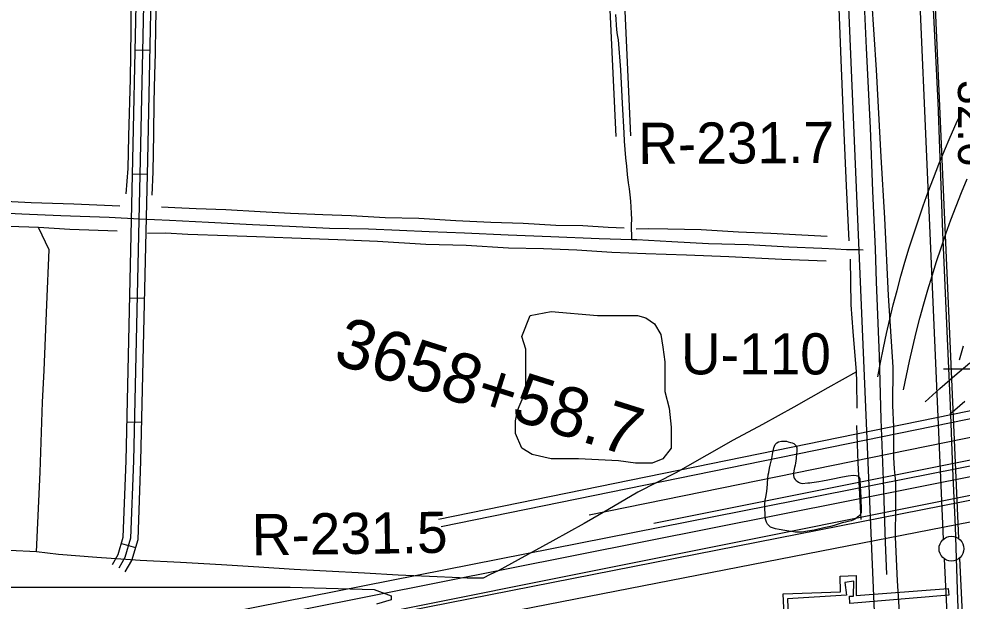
# Model space of a CAD drawing. Extents: x 3313447 to 3351316, y 703786 to 729172.
# Drawn here: x 3320382 to 3322283, y 721813 to 722988 of the extents above; entities that cross this region are included whole.
import ezdxf

# ---------------------------------------------------------------- set-up
doc = ezdxf.new("R2010")
doc.units = 0
for name, color, linetype in [('V-DTCH-CNTR', 7, 'Continuous'), ('V-FLOD-BASE', 7, 'Continuous'), ('V-LEVE-TOET', 7, 'Continuous'), ('V-RIVR-RANG', 7, 'Continuous'), ('V-RIVR-RANG-IDEN', 7, 'Continuous'), ('V-ROAD-CNTR', 7, 'Continuous'), ('V-SITE-VEGE', 7, 'Continuous'), ('V-SURV-IDEN', 7, 'Continuous'), ('V-SURV-LINE', 7, 'Continuous'), ('V-TOPO-SHOR', 7, 'Continuous'), ('V-UTIL-LINE', 7, 'Continuous')]:
    doc.layers.add(name, color=color, linetype=linetype)

msp = doc.modelspace()

# ---------------------------------------------------------------- linework, layer by layer
at = {"layer": 'V-DTCH-CNTR'}
msp.add_lwpolyline([(3321617.4, 722542.8), (3321616.9, 722552.9), (3321616.7, 722562.9), (3321616.6, 722573), (3321616.8, 722583.1), (3321616.4, 722595.5), (3321615.7, 722607.8), (3321614.8, 722620.1), (3321613.7, 722632.4), (3321612.3, 722644.7), (3321610.7, 722656.9), (3321608.6, 722673.7), (3321606.7, 722690.5), (3321605.1, 722707.3), (3321603.7, 722724.1), (3321602.5, 722741), (3321601.6, 722757.9), (3321598.2, 722816.7), (3321594.6, 722884.5), (3321589.9, 722945.4), (3321588.4, 722955.5), (3321587.2, 722965.7), (3321586.3, 722975.8), (3321585.6, 722986), (3321585.1, 722996.2)], dxfattribs=at)
at = {"layer": 'V-FLOD-BASE'}
msp.add_lwpolyline([(3322294, 721368.1), (3322281.2, 721662.8), (3322274.1, 721816), (3322269.7, 721963), (3322263.9, 722080.1), (3322259.4, 722208.1), (3322252.3, 722357.9), (3322244, 722557.3), (3322234.5, 722819.4), (3322223.5, 723034.5), (3322212.5, 723259.8), (3322203.5, 723485.2), (3322191.4, 723776.5), (3322185.6, 723936.5), (3322185.3, 724050.8), (3322186.1, 724129.8), (3322189, 724191.7), (3322188.8, 724355.1), (3322190.1, 724588.6), (3322195.6, 724641), (3322197.1, 724671.6), (3322196.5, 724713.1), (3322192.5, 724744.4), (3322195.1, 724942.5)], dxfattribs=at)
at = {"layer": 'V-LEVE-TOET'}
msp.add_lwpolyline([(3322064.2, 723842.4), (3322068.6, 723720.7), (3322071, 723652.9), (3322073, 723597), (3322079.6, 723543.2), (3322085.5, 723402.8), (3322091.4, 723242.7), (3322096.9, 723129.5), (3322100.2, 723028), (3322109.2, 722884.9), (3322118.7, 722709.5), (3322126.2, 722585.8), (3322133.6, 722429.4), (3322143.2, 722285.3), (3322142.6, 722207.6), (3322144.3, 722164.8), (3322144.7, 722103.2), (3322145.5, 722079.9), (3322148.3, 722053.3), (3322148.6, 721983.9), (3322147.7, 721962.7), (3322148, 721942.1), (3322151.5, 721854.1), (3322156.6, 721781.2)], dxfattribs=at)
at = {"layer": 'V-RIVR-RANG'}
msp.add_line((3322245.2, 722282), (3323045.2, 722282.9), dxfattribs=at)
at = {"layer": 'V-ROAD-CNTR'}
for p, q in [((3320616.1, 722924.8), (3320646.1, 722924.2)), ((3320610.8, 722674.9), (3320640.8, 722674.2)), ((3320605.1, 722425), (3320635.1, 722424.3)), ((3320599.5, 722175), (3320629.5, 722174.4)), ((3320588.3, 721929.7), (3320617.1, 721921.2))]:
    msp.add_line(p, q, dxfattribs=at)
for points in [[(3322139.1, 720885.8), (3322130.7, 721205.1), (3322096.5, 722014), (3322054, 723027.2), (3322033, 723634.2), (3322026.6, 723817.2)], [(3321545.5, 723567.8), (3321569, 723091.8), (3321584.6, 722750.1)], [(3321575.6, 723566.5), (3321599, 723093.2), (3321614.6, 722751.4)], [(3320641.2, 723540.4), (3320638.4, 723265.5), (3320626.4, 722703.2), (3320612.7, 722095.9), (3320607, 721940.2), (3320595.6, 721901.3), (3320583.2, 721879.8)], [(3320596.2, 721872.3), (3320609.5, 721895.3), (3320621.9, 721937.7), (3320627.7, 722095.4), (3320641.4, 722702.9), (3320653.4, 723265.3), (3320656.1, 723530.3)], [(3320570.2, 721887.2), (3320581.7, 721907.2), (3320592.1, 721942.6), (3320597.7, 722096.3), (3320611.4, 722703.5), (3320623.4, 723265.7), (3320624.9, 723411.2)], [(3319290.7, 722638.8), (3319343.4, 722637.7), (3319419.2, 722635.4), (3319510.4, 722631.3), (3319596.3, 722628.7), (3319698.5, 722624.6), (3319791.3, 722620.6), (3319890.1, 722615.8), (3319970.8, 722611.8), (3320071, 722606.7), (3320163.8, 722603), (3320240, 722599.6), (3320307.2, 722598.1), (3320388, 722594.4), (3320466.6, 722591.1), (3320563.6, 722587.4), (3320624.6, 722584.4), (3320685.6, 722581.5)], [(3320685.6, 722581.5), (3320763.9, 722577.8), (3320852.3, 722573.1), (3320927.4, 722569.8), (3321007.8, 722565.7), (3321086.1, 722564.1), (3321149, 722561.5), (3321208.5, 722558.9), (3321279.9, 722556), (3321368.2, 722552.2), (3321453.8, 722548.9), (3321551.6, 722544.5), (3321617.4, 722542.8), (3321627.1, 722542.5), (3321697.7, 722538.5), (3321771.8, 722534.8), (3321851.5, 722532.2), (3321933.3, 722527.5), (3321999.7, 722524.9), (3322027.5, 722524.1), (3322049.5, 722522.6), (3322064.4, 722522.3), (3322074.2, 722522.2), (3322083.1, 722521.8)]]:
    msp.add_lwpolyline(points, dxfattribs=at)
at = {"layer": 'V-SITE-VEGE'}
msp.add_lwpolyline([(3321548, 722389.2), (3321628.7, 722389.2), (3321645.6, 722384.9), (3321662.6, 722372.2), (3321675.4, 722350.9), (3321679.6, 722325.5), (3321683.8, 722295.7), (3321683.8, 722236.2), (3321692.3, 722202.3), (3321696.6, 722164), (3321696.6, 722121.5), (3321679.6, 722100.3), (3321658.4, 722091.8), (3321624.4, 722091.8), (3321590.4, 722096.1), (3321509.8, 722100.3), (3321454.6, 722100.3), (3321416.4, 722108.8), (3321395.2, 722121.5), (3321382.4, 722151.3), (3321382.4, 722176.8), (3321386.7, 722198), (3321399.4, 722227.7), (3321403.6, 722249), (3321403.6, 722321.2), (3321395.2, 722346.7), (3321412.1, 722389.2), (3321454.6, 722397.7)], close=True, dxfattribs=at)
for points in [[(3321948.2, 722056.7), (3321950.4, 722055), (3321952.9, 722053.4), (3321955.9, 722052), (3321957.8, 722051.3), (3321960.5, 722050.6), (3321971.6, 722051.8), (3321975.7, 722051.9), (3321979.6, 722052.4), (3321984.7, 722052.9), (3321994.1, 722054.5), (3322001.3, 722055.8), (3322011.8, 722058), (3322018.6, 722059.2), (3322041.4, 722063.9), (3322053.3, 722066.1), (3322063.2, 722067.2), (3322068.9, 722066.8), (3322071.7, 722066), (3322073.8, 722065.1), (3322076.4, 722060.7), (3322076.9, 722057.4), (3322077.4, 722045.1), (3322078.8, 722022.1), (3322078.8, 722014.2), (3322079.1, 722002.8), (3322079.1, 721999.2), (3322079.4, 721996.4), (3322079.4, 721993.8), (3322079, 721991.1), (3322077.8, 721988.6), (3322076.4, 721986.6), (3322074.5, 721984.4), (3322072.2, 721982.5), (3322067.6, 721979.3), (3322062.6, 721976.7), (3322058.8, 721975.5), (3322052.6, 721973.6), (3322048, 721972.5), (3322041.2, 721970.9), (3322025, 721966.1), (3322017.4, 721964.1), (3322004, 721960.8), (3321984.8, 721956.6), (3321971.4, 721954.1), (3321959.9, 721952.6), (3321955.8, 721952.5), (3321950, 721952.5), (3321946.6, 721952.6), (3321938.7, 721953.6), (3321933.6, 721954.4), (3321925.5, 721955.4), (3321913.7, 721957.4), (3321906.8, 721958.9), (3321902.5, 721960.3), (3321896.8, 721962.7), (3321893.9, 721964.9), (3321890.4, 721968.8), (3321888.7, 721972.4), (3321886.8, 721978.9), (3321885.9, 721986.9), (3321885.4, 722002), (3321885.4, 722008.2), (3321886.1, 722017), (3321886.9, 722023), (3321888.9, 722034.6), (3321890.5, 722049.1), (3321890.5, 722052), (3321891.3, 722060.5), (3321892.1, 722067.8), (3321893, 722073), (3321894.7, 722081.5), (3321896.1, 722087.2), (3321897.8, 722095.6), (3321899.1, 722100.8), (3321901.5, 722112.8), (3321902.8, 722118.9), (3321903.5, 722122.6), (3321904.4, 722125.9), (3321905.7, 722129.4), (3321909, 722132.8), (3321912.9, 722134.5), (3321918.9, 722135.6), (3321922.6, 722136), (3321925.2, 722136), (3321928.8, 722135.6), (3321932.2, 722134.8), (3321936.8, 722133.5), (3321939.9, 722132.4), (3321943.3, 722131), (3321945.1, 722129.7), (3321948, 722126.5), (3321949.7, 722122.6), (3321949.9, 722120.1), (3321949.5, 722114.6), (3321949.1, 722111.9), (3321948.2, 722101.1), (3321947, 722091.2), (3321946.3, 722087.8), (3321944.9, 722082.7), (3321943.4, 722075.8)], [(3321943.4, 722075.8), (3321943, 722071.5), (3321943.1, 722066.9), (3321943.6, 722063.5), (3321944.4, 722061.5), (3321946, 722058.8), (3321948.2, 722056.7)], [(3319964.4, 721811.4), (3320011.1, 721828.4), (3320057.8, 721849.7), (3320147, 721858.2), (3320359.3, 721841.2), (3320928.2, 721841.2), (3321098, 721836.9), (3321131.9, 721824.2), (3321131.9, 721815.7), (3321102.2, 721807.2)]]:
    msp.add_lwpolyline(points, dxfattribs=at)
at = {"layer": 'V-SURV-LINE'}
for points in [[(3322245.5, 721938.3), (3322163.8, 723805.4)], [(3322193.8, 723806.7), (3322275.4, 721939.6)], [(3322306.7, 720667.9), (3322247.3, 721898.3)], [(3322277.3, 721899.7), (3322336.6, 720669.3)]]:
    msp.add_lwpolyline(points, dxfattribs=at)
msp.add_circle((3322261.3, 721919), 25, dxfattribs=at)
at = {"layer": 'V-TOPO-SHOR'}
for points in [[(3322131.3, 721867.2), (3322128.2, 721932.4), (3322124.6, 722057.9), (3322119.9, 722180), (3322116.2, 722307), (3322110.3, 722457.5), (3322107.9, 722523.5), (3322103.1, 722640.3), (3322098.2, 722768.1), (3322090, 722928.3), (3322083.8, 723062.5), (3322078.9, 723206.3), (3322075, 723318.1), (3322071.1, 723447.7), (3322068, 723548.8)], [(3320650.5, 722632), (3320652.4, 722679), (3320653.6, 722755.9), (3320654.5, 722819.6), (3320655.7, 722875.6), (3320657.2, 722918), (3320657.7, 722974.1), (3320659.9, 723040.9), (3320662.5, 723093.1), (3320662.7, 723164.4), (3320662.8, 723226.7), (3320665.5, 723301.8), (3320667, 723355.1), (3320668.2, 723402.7), (3320670.5, 723420.1)], [(3320597.7, 722635), (3320602.3, 722686.1), (3320603.5, 722751.2), (3320606.9, 722866.7), (3320607.9, 722964.5), (3320608, 723011.1), (3320609.2, 723054.6), (3320611.4, 723115.1), (3320614.4, 723181.9), (3320614.5, 723249.1), (3320616.5, 723314.5), (3320617.9, 723353.8), (3320618, 723402.7)], [(3322055.2, 722539.6), (3322049.4, 722650.6), (3322045.3, 722758), (3322039.2, 722904.8), (3322036.4, 722974.5), (3322031, 723111.9), (3322027, 723194.8), (3322024.3, 723256.7)], [(3320585.5, 722609.9), (3320492.4, 722613.7), (3320406.4, 722616.3), (3320340.5, 722619.7)], [(3321601.9, 722565.4), (3321569.3, 722567), (3321518.5, 722569.9), (3321464.2, 722571.1), (3321398.1, 722575.1), (3321333.1, 722577), (3321262.5, 722580.3), (3321188, 722584.7), (3321120.1, 722586.6), (3321051.6, 722590.3), (3320994.2, 722592.2), (3320929.5, 722594.8), (3320868.3, 722598.1), (3320798.7, 722602.1), (3320739.2, 722604.7), (3320696.4, 722606.2), (3320669.2, 722607.6)], [(3320580, 722559.7), (3320484.2, 722562.9), (3320421.6, 722566.5), (3320362.1, 722569.1), (3320281.1, 722573.2), (3320181.9, 722577.6), (3320095.3, 722582.4), (3319987.8, 722586.1), (3319888.6, 722591.2), (3319787.7, 722595), (3319670.1, 722600.2), (3319589, 722604.5), (3319509.6, 722605.1)], [(3320417.6, 721912.9), (3320424.9, 722073.4), (3320429.1, 722214.6), (3320433, 722278.5), (3320438.4, 722411.2), (3320443.1, 722521.5), (3320421.6, 722566.5)], [(3322008.8, 722499.1), (3321919.4, 722502.5), (3321812.6, 722507.6), (3321727, 722511), (3321645.6, 722514), (3321577.1, 722516.2), (3321506.1, 722520.9), (3321438.9, 722523.5), (3321368.3, 722525.1), (3321283.4, 722530.2), (3321201.7, 722532.8), (3321104.6, 722538.3), (3321024.9, 722541.7), (3320932, 722545), (3320860.4, 722548.3), (3320802.2, 722550.2), (3320722.6, 722552.9), (3320677, 722555.4), (3320640.9, 722555)], [(3322010.8, 722548.5), (3321960, 722551), (3321897.1, 722554.7), (3321832, 722557.3), (3321756.5, 722562), (3321689.7, 722563.2), (3321650.7, 722564.4), (3321625.5, 722563.1)], [(3322071.3, 722202.7), (3322070.8, 722256.1), (3322069.9, 722275.8), (3322063.3, 722356.9), (3322059.4, 722410.9), (3322058.1, 722502.9)], [(3322069.9, 722275.8), (3322011.9, 722243.3), (3321943.3, 722204.5), (3321880.2, 722169.2), (3321821.3, 722138), (3321768.4, 722107.9), (3321705.6, 722071.9), (3321629, 722033.1), (3321569, 721997.1), (3321521, 721970.1), (3321457.9, 721935.1), (3321387.8, 721896.3), (3321347.8, 721874.5), (3321331.4, 721866.9), (3321317.5, 721859.6), (3321309.8, 721859.3), (3321285.4, 721859.3), (3321224.6, 721862.6), (3321146.3, 721865.9), (3321078.4, 721869.6), (3321000.8, 721873.6), (3320936.5, 721877.3), (3320865.2, 721882), (3320790, 721886.7), (3320707.6, 721891.1), (3320626.1, 721895.5), (3320538.8, 721901.3), (3320461.9, 721907.4), (3320417.6, 721912.9), (3320363.1, 721915.3)], [(3322079.6, 721977.9), (3322073.5, 722091.9), (3322070.8, 722167.6)]]:
    msp.add_lwpolyline(points, dxfattribs=at)
at = {"layer": 'V-UTIL-LINE'}
for p, q in [((3319986, 721562.2), (3327138.8, 722968.5)), ((3321227.4, 721978.9), (3326071.1, 722968.5)), ((3321233.1, 721963.5), (3326076.9, 722953.1)), ((3320012.1, 721527.5), (3327138.8, 722916.4)), ((3320480.8, 721727.1), (3326505.1, 722916.4)), ((3320472.2, 721701.1), (3326453.1, 722890.3)), ((3320498.2, 721666.4), (3326435.7, 722855.6)), ((3321531.2, 721987.6), (3325671.8, 722829.6)), ((3321661.4, 721970.2), (3325515.6, 722742.8)), ((3322254.7, 721838.5), (3322256, 721825.4))]:
    msp.add_line(p, q, dxfattribs=at)
for points in [[(3322112.8, 722265.3), (3322118.2, 722294.6), (3322124.1, 722323.8), (3322130.4, 722353), (3322137, 722382), (3322144.1, 722411), (3322151.5, 722439.8), (3322159.3, 722468.6), (3322167.5, 722497.2), (3322176.2, 722525.8), (3322185.2, 722554.2), (3322194.5, 722582.4), (3322204.3, 722610.6), (3322214.5, 722638.6), (3322225, 722666.5), (3322235.9, 722694.2), (3322247.2, 722721.8), (3322258.8, 722749.2), (3322270.9, 722776.5), (3322283.3, 722803.6)], [(3322164.9, 722239.3), (3322170.6, 722268.4), (3322176.8, 722297.4), (3322183.4, 722326.4), (3322190.3, 722355.2), (3322197.7, 722384), (3322205.4, 722412.6), (3322213.6, 722441.2), (3322222.1, 722469.6), (3322231, 722497.9), (3322240.4, 722526.1), (3322250.1, 722554.1), (3322260.2, 722582), (3322270.6, 722609.8), (3322281.5, 722637.4), (3322292.7, 722664.9)], [(3322277.7, 722300.1), (3322285.6, 722328.2)], [(3322208.2, 722215.1), (3322238.1, 722241.8), (3322268.2, 722268.1), (3322298.6, 722294.1)], [(3322257.8, 722190.4), (3322288.5, 722216.4)], [(3322256, 721825.4), (3322056.7, 721808.8), (3322056, 721823.2), (3322063.6, 721823.2), (3322064.3, 721853.4), (3322046.5, 721850.7), (3322049.8, 721825.3), (3321930.9, 721818), (3321935.4, 721693.6), (3321931.3, 721693), (3321930.6, 721696.4), (3321922.4, 721696.4), (3321921, 721688.9), (3321917.5, 721689.6), (3321916.9, 721699.9), (3321927.9, 721700.5), (3321922, 721827.7), (3322037.5, 721832.2), (3322036.9, 721863.8), (3322069.2, 721865.1), (3322069.1, 721824.5), (3322254.7, 721838.5)]]:
    msp.add_lwpolyline(points, dxfattribs=at)

# ---------------------------------------------------------------- texts
at = {"layer": 'V-RIVR-RANG'}
msp.add_text('32.6', height=67, rotation=270.1583, dxfattribs=at).set_placement((3322274.2, 722864.2))
at = {"layer": 'V-RIVR-RANG-IDEN'}
for s, rotation, p in [('R-231.7', 0.3044, (3321630, 722694.9)), ('U-110', 359.9644, (3321716, 722270.6)), ('R-231.5', 0.7664, (3320851.4, 721905.6))]:
    msp.add_text(s, height=83, rotation=rotation, dxfattribs=at).set_placement(p)
at = {"layer": 'V-SURV-IDEN'}
msp.add_text('3658+58.7', height=100, rotation=342.5113, dxfattribs=at).set_placement((3321012.4, 722293.7))

doc.saveas('drawing.dxf')
